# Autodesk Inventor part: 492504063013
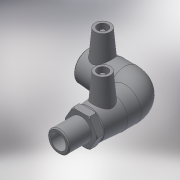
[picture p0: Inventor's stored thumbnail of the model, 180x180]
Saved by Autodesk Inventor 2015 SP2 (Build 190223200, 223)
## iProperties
Created: 2017-06
Part Number: 492504063013
Material: Generic
Description: PLASSON 90° ELBOW MALE TRANSITION 63-1.1/4"
Document SubType Name: Modeling
Designer: KIM
Mass: 483.809 g
Surface Area: 949.499 cm^2
Volume: 483.809 cm^3
Density: 1 g/cm^3
Appearance: Default
Author: KIM
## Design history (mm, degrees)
derived "492504.ipt"
feature "Solid1::492504.ipt"
tag "TaggingFeature1"
body "Solid1"
other parameters: "d2" = 82, "d4" = 43.66667, "d5" = 73.8, "d8" = 168 deg, "d10" = 22.8, "d11" = 7.6, "d29" = 59, "d30" = 15, "d31" = 72.05, "d34" = 5 deg, "d41" = 4, "d42" = 14, "d43" = 0, "d49" = 63, "d50" = 53.55, "d51" = 22.8, "d52" = 57, "d54" = 90 deg, "d57" = 63, "d58" = 57, "d59" = 0, "d61" = 90 deg, "d86" = 3, "d87" = 0, "d93" = 0.1, "d94" = 9, "d95" = 41.91, "d96" = 29.337, "d97" = 48, "d98" = 36, "d99" = 82, "d100" = 32.4, "d102" = 2.52, "d106" = 0, "d_" = 63, "L_" = 167, "L_1" = 57, "D_" = 48, "A_" = 59, "d_2" = 12, "L_2" = 36, "D_1" = 82, "R_" = 41.91
